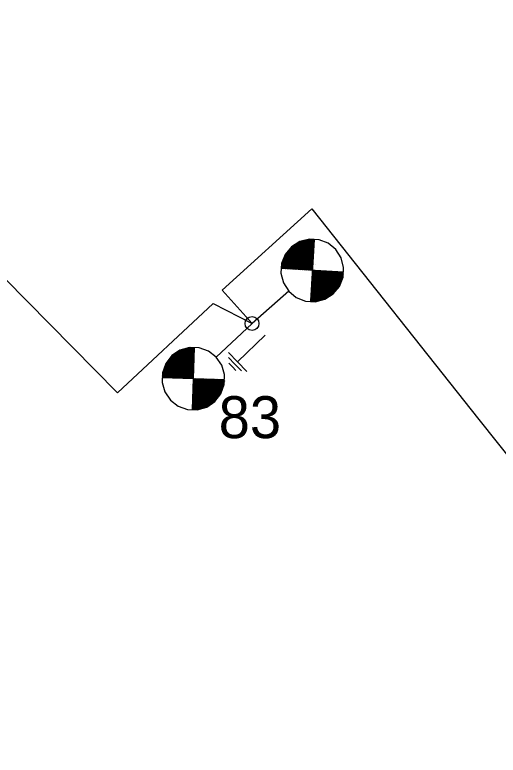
# Model space of a CAD drawing. Extents: x 25497851 to 25498523, y 6686544 to 6687372.
# Drawn here: x 25498375.6 to 25498410.2, y 6687202.5 to 6687255.4 of the extents above; entities that cross this region are included whole.
import ezdxf

# ---------------------------------------------------------------- set-up
doc = ezdxf.new("R2010")
doc.units = 0
for name, color, linetype in [('EL_CABLE_MAA', 7, 'Continuous'), ('KEYGWT_ANNOTATION', 7, 'Continuous'), ('Level 17', 7, 'Continuous'), ('Level 63', 7, 'Continuous'), ('Taso 1', 7, 'Continuous'), ('Taso 50', 7, 'Continuous')]:
    doc.layers.add(name, color=color, linetype=linetype)

msp = doc.modelspace()

# ---------------------------------------------------------------- linework, layer by layer
at = {"layer": 'EL_CABLE_MAA'}
for points in [[(25498357.846, 6687255.44), (25498370.073, 6687241.504), (25498382.973, 6687228.409), (25498389.816, 6687234.786), (25498392.6, 6687233.365)], [(25498392.6, 6687233.365), (25498390.456, 6687235.761), (25498396.873, 6687241.567), (25498408.81, 6687226.51), (25498414.146, 6687219.815), (25498426.734, 6687207.772), (25498433.268, 6687202.5), (25498436.712, 6687203.691)]]:
    msp.add_lwpolyline(points, dxfattribs=at)
at = {"layer": 'Level 17'}
for points in [[(25498393.533, 6687232.534), (25498391.572, 6687230.634)], [(25498391.572, 6687230.626), (25498390.914, 6687231.305)], [(25498391.383, 6687230.46), (25498390.917, 6687230.941)], [(25498392.23, 6687229.947), (25498391.572, 6687230.626)], [(25498390.936, 6687230.543), (25498391.194, 6687230.276)], [(25498391.194, 6687230.276), (25498391.452, 6687230.01)], [(25498391.849, 6687229.978), (25498391.383, 6687230.46)]]:
    msp.add_lwpolyline(points, dxfattribs=at)
at = {"layer": 'Taso 1'}
for p, q in [((25498397.052, 6687239.384), (25498396.773, 6687234.949)), ((25498399.13, 6687237.028), (25498394.695, 6687237.307)), ((25498395.225, 6687235.68), (25498392.6, 6687233.365)), ((25498390.048, 6687230.969), (25498392.6, 6687233.365)), ((25498388.338, 6687227.209), (25498388.478, 6687231.65)), ((25498386.188, 6687229.499), (25498390.63, 6687229.359))]:
    msp.add_line(p, q, dxfattribs=at)
for points in [[(25498398.599, 6687238.654), (25498398.057, 6687239.103), (25498397.403, 6687239.362), (25498396.7, 6687239.407), (25498396.019, 6687239.232), (25498395.424, 6687238.855), (25498394.976, 6687238.312), (25498394.717, 6687237.658), (25498394.673, 6687236.956), (25498394.848, 6687236.274), (25498395.225, 6687235.68), (25498395.768, 6687235.231), (25498396.422, 6687234.972), (25498397.124, 6687234.927), (25498397.806, 6687235.102), (25498398.4, 6687235.479), (25498398.849, 6687236.021), (25498399.108, 6687236.676), (25498399.152, 6687237.378), (25498398.977, 6687238.06)], [(25498386.769, 6687227.89), (25498387.326, 6687227.458), (25498387.988, 6687227.22), (25498388.691, 6687227.198), (25498389.367, 6687227.394), (25498389.949, 6687227.789), (25498390.38, 6687228.345), (25498390.619, 6687229.007), (25498390.641, 6687229.711), (25498390.444, 6687230.387), (25498390.048, 6687230.969), (25498389.492, 6687231.401), (25498388.83, 6687231.639), (25498388.127, 6687231.661), (25498387.451, 6687231.465), (25498386.869, 6687231.07), (25498386.437, 6687230.514), (25498386.199, 6687229.851), (25498386.177, 6687229.148), (25498386.374, 6687228.472)]]:
    msp.add_lwpolyline(points, close=True, dxfattribs=at)
msp.add_circle((25498392.6, 6687233.365), 0.5, dxfattribs=at)
at = {"layer": 'Taso 50'}
for p, q in [((25498395.721, 6687239.043), (25498396.942, 6687237.659)), ((25498396.948, 6687237.732), (25498395.791, 6687239.045)), ((25498395.829, 6687239.078), (25498396.953, 6687237.803)), ((25498395.866, 6687239.111), (25498396.957, 6687237.873)), ((25498395.904, 6687239.144), (25498396.962, 6687237.944)), ((25498395.941, 6687239.177), (25498396.966, 6687238.014)), ((25498396.971, 6687238.085), (25498395.979, 6687239.21)), ((25498396.975, 6687238.156), (25498396.049, 6687239.206)), ((25498396.98, 6687238.226), (25498396.087, 6687239.239)), ((25498396.984, 6687238.297), (25498396.157, 6687239.234)), ((25498396.988, 6687238.367), (25498396.195, 6687239.267)), ((25498396.993, 6687238.438), (25498396.265, 6687239.263)), ((25498396.997, 6687238.508), (25498396.303, 6687239.296)), ((25498397.002, 6687238.579), (25498396.374, 6687239.292)), ((25498397.006, 6687238.65), (25498396.411, 6687239.325)), ((25498397.011, 6687238.72), (25498396.482, 6687239.32)), ((25498397.015, 6687238.791), (25498396.519, 6687239.353)), ((25498397.02, 6687238.861), (25498396.59, 6687239.349)), ((25498397.024, 6687238.932), (25498396.627, 6687239.382)), ((25498397.028, 6687239.002), (25498396.698, 6687239.377)), ((25498397.033, 6687239.073), (25498396.768, 6687239.373)), ((25498397.037, 6687239.144), (25498396.806, 6687239.406)), ((25498397.042, 6687239.214), (25498396.876, 6687239.402)), ((25498397.046, 6687239.285), (25498396.98, 6687239.36)), ((25498396.348, 6687237.203), (25498395.191, 6687238.516)), ((25498396.419, 6687237.199), (25498395.2, 6687238.584)), ((25498396.49, 6687237.194), (25498395.233, 6687238.619)), ((25498396.56, 6687237.19), (25498395.271, 6687238.652)), ((25498396.631, 6687237.185), (25498395.308, 6687238.686)), ((25498396.701, 6687237.181), (25498395.346, 6687238.719)), ((25498396.772, 6687237.176), (25498395.383, 6687238.752)), ((25498395.388, 6687238.822), (25498396.842, 6687237.172)), ((25498395.424, 6687238.855), (25498396.913, 6687237.167)), ((25498395.463, 6687238.888), (25498396.917, 6687237.238)), ((25498395.533, 6687238.884), (25498396.922, 6687237.309)), ((25498395.571, 6687238.917), (25498396.926, 6687237.379)), ((25498395.608, 6687238.95), (25498396.931, 6687237.45)), ((25498395.646, 6687238.983), (25498396.902, 6687237.558)), ((25498396.94, 6687237.591), (25498395.683, 6687239.016)), ((25498395.572, 6687237.252), (25498394.878, 6687238.04)), ((25498395.643, 6687237.247), (25498394.915, 6687238.073)), ((25498395.713, 6687237.243), (25498394.92, 6687238.143)), ((25498395.784, 6687237.239), (25498394.957, 6687238.176)), ((25498395.854, 6687237.234), (25498394.962, 6687238.247)), ((25498395.925, 6687237.23), (25498394.999, 6687238.28)), ((25498395.996, 6687237.225), (25498395.037, 6687238.313)), ((25498396.066, 6687237.221), (25498395.074, 6687238.346)), ((25498396.137, 6687237.216), (25498395.079, 6687238.417)), ((25498396.207, 6687237.212), (25498395.116, 6687238.45)), ((25498396.278, 6687237.208), (25498395.154, 6687238.483)), ((25498394.866, 6687237.296), (25498394.701, 6687237.484)), ((25498394.937, 6687237.292), (25498394.706, 6687237.554)), ((25498395.008, 6687237.287), (25498394.743, 6687237.587)), ((25498395.078, 6687237.283), (25498394.747, 6687237.658)), ((25498395.149, 6687237.279), (25498394.752, 6687237.729)), ((25498395.219, 6687237.274), (25498394.789, 6687237.762)), ((25498395.29, 6687237.27), (25498394.794, 6687237.832)), ((25498395.36, 6687237.265), (25498394.831, 6687237.865)), ((25498395.431, 6687237.261), (25498394.836, 6687237.936)), ((25498395.502, 6687237.256), (25498394.873, 6687237.969)), ((25498397.118, 6687237.615), (25498397.118, 6687237.615)), ((25498394.796, 6687237.301), (25498394.697, 6687237.413)), ((25498396.9, 6687236.956), (25498398.255, 6687235.418)), ((25498396.904, 6687237.026), (25498398.293, 6687235.451)), ((25498396.909, 6687237.097), (25498398.363, 6687235.447)), ((25498396.912, 6687237.168), (25498398.4, 6687235.479)), ((25498396.984, 6687237.163), (25498398.438, 6687235.513)), ((25498397.054, 6687237.159), (25498398.443, 6687235.583)), ((25498397.125, 6687237.154), (25498398.48, 6687235.616)), ((25498397.195, 6687237.15), (25498398.518, 6687235.65)), ((25498397.266, 6687237.145), (25498398.555, 6687235.683)), ((25498397.336, 6687237.141), (25498398.593, 6687235.716)), ((25498397.407, 6687237.136), (25498398.625, 6687235.75)), ((25498397.478, 6687237.132), (25498398.635, 6687235.819)), ((25498397.548, 6687237.128), (25498398.672, 6687235.852)), ((25498397.619, 6687237.123), (25498398.71, 6687235.885)), ((25498397.689, 6687237.119), (25498398.747, 6687235.919)), ((25498397.76, 6687237.114), (25498398.785, 6687235.952)), ((25498397.83, 6687237.11), (25498398.822, 6687235.985)), ((25498397.901, 6687237.105), (25498398.849, 6687236.021)), ((25498397.972, 6687237.101), (25498398.864, 6687236.088)), ((25498398.042, 6687237.097), (25498398.869, 6687236.159)), ((25498398.113, 6687237.092), (25498398.906, 6687236.192)), ((25498398.183, 6687237.088), (25498398.911, 6687236.263)), ((25498398.254, 6687237.083), (25498398.948, 6687236.296)), ((25498398.324, 6687237.079), (25498398.953, 6687236.366)), ((25498398.395, 6687237.074), (25498398.99, 6687236.399)), ((25498398.466, 6687237.07), (25498398.995, 6687236.47)), ((25498398.536, 6687237.065), (25498399.032, 6687236.503)), ((25498398.607, 6687237.061), (25498399.037, 6687236.573)), ((25498398.677, 6687237.057), (25498399.074, 6687236.606)), ((25498398.748, 6687237.052), (25498399.113, 6687236.638)), ((25498398.818, 6687237.048), (25498399.083, 6687236.748)), ((25498398.889, 6687237.043), (25498399.087, 6687236.818)), ((25498398.96, 6687237.039), (25498399.125, 6687236.851)), ((25498399.03, 6687237.034), (25498399.129, 6687236.922)), ((25498396.864, 6687236.391), (25498397.922, 6687235.191)), ((25498396.869, 6687236.462), (25498397.96, 6687235.224)), ((25498396.873, 6687236.532), (25498397.997, 6687235.257)), ((25498396.877, 6687236.603), (25498398.035, 6687235.29)), ((25498396.882, 6687236.674), (25498398.103, 6687235.291)), ((25498396.886, 6687236.744), (25498398.143, 6687235.319)), ((25498396.891, 6687236.815), (25498398.18, 6687235.352)), ((25498396.895, 6687236.885), (25498398.218, 6687235.385)), ((25498396.833, 6687235.897), (25498397.56, 6687235.072)), ((25498396.837, 6687235.968), (25498397.631, 6687235.068)), ((25498396.842, 6687236.038), (25498397.669, 6687235.101)), ((25498396.846, 6687236.109), (25498397.739, 6687235.096)), ((25498396.851, 6687236.18), (25498397.806, 6687235.102)), ((25498396.855, 6687236.25), (25498397.847, 6687235.125)), ((25498396.86, 6687236.321), (25498397.885, 6687235.158)), ((25498396.798, 6687235.333), (25498397.128, 6687234.958)), ((25498396.802, 6687235.403), (25498397.199, 6687234.953)), ((25498396.806, 6687235.474), (25498397.236, 6687234.986)), ((25498396.811, 6687235.544), (25498397.307, 6687234.982)), ((25498396.815, 6687235.615), (25498397.344, 6687235.015)), ((25498396.82, 6687235.686), (25498397.415, 6687235.01)), ((25498396.824, 6687235.756), (25498397.472, 6687235.021)), ((25498396.829, 6687235.827), (25498397.523, 6687235.039)), ((25498396.78, 6687235.05), (25498396.879, 6687234.938)), ((25498396.784, 6687235.121), (25498396.95, 6687234.933)), ((25498396.789, 6687235.192), (25498397.02, 6687234.929)), ((25498396.793, 6687235.262), (25498397.091, 6687234.925)), ((25498388.464, 6687231.196), (25498388.053, 6687231.633)), ((25498388.466, 6687231.266), (25498388.124, 6687231.631)), ((25498388.468, 6687231.337), (25498388.16, 6687231.665)), ((25498388.47, 6687231.408), (25498388.231, 6687231.663)), ((25498388.473, 6687231.478), (25498388.302, 6687231.661)), ((25498388.475, 6687231.549), (25498388.372, 6687231.658)), ((25498388.41, 6687229.5), (25498386.904, 6687231.103)), ((25498388.413, 6687229.57), (25498386.975, 6687231.101)), ((25498388.415, 6687229.641), (25498387.012, 6687231.135)), ((25498388.417, 6687229.712), (25498387.048, 6687231.169)), ((25498388.419, 6687229.782), (25498387.084, 6687231.204)), ((25498388.422, 6687229.853), (25498387.121, 6687231.238)), ((25498388.424, 6687229.924), (25498387.16, 6687231.267)), ((25498388.426, 6687229.994), (25498387.228, 6687231.27)), ((25498388.428, 6687230.065), (25498387.265, 6687231.304)), ((25498388.43, 6687230.136), (25498387.301, 6687231.338)), ((25498388.433, 6687230.206), (25498387.337, 6687231.373)), ((25498388.435, 6687230.277), (25498387.374, 6687231.407)), ((25498388.437, 6687230.348), (25498387.41, 6687231.441)), ((25498388.439, 6687230.418), (25498387.451, 6687231.465)), ((25498388.442, 6687230.489), (25498387.517, 6687231.473)), ((25498388.444, 6687230.56), (25498387.588, 6687231.471)), ((25498388.446, 6687230.63), (25498387.625, 6687231.505)), ((25498388.448, 6687230.701), (25498387.695, 6687231.503)), ((25498388.45, 6687230.772), (25498387.732, 6687231.537)), ((25498388.453, 6687230.842), (25498387.782, 6687231.557)), ((25498388.455, 6687230.913), (25498387.839, 6687231.569)), ((25498388.457, 6687230.984), (25498387.909, 6687231.567)), ((25498388.459, 6687231.054), (25498387.946, 6687231.601)), ((25498388.462, 6687231.125), (25498388.017, 6687231.599)), ((25498387.56, 6687229.456), (25498386.499, 6687230.585)), ((25498387.631, 6687229.453), (25498386.536, 6687230.62)), ((25498387.702, 6687229.451), (25498386.572, 6687230.654)), ((25498387.772, 6687229.449), (25498386.608, 6687230.688)), ((25498387.843, 6687229.447), (25498386.645, 6687230.722)), ((25498387.914, 6687229.444), (25498386.653, 6687230.792)), ((25498387.984, 6687229.442), (25498386.684, 6687230.827)), ((25498388.055, 6687229.44), (25498386.72, 6687230.861)), ((25498388.126, 6687229.438), (25498386.756, 6687230.896)), ((25498388.196, 6687229.436), (25498386.793, 6687230.93)), ((25498388.267, 6687229.433), (25498386.829, 6687230.964)), ((25498388.338, 6687229.431), (25498386.832, 6687231.035)), ((25498388.409, 6687229.429), (25498386.869, 6687231.07)), ((25498386.853, 6687229.478), (25498386.306, 6687230.061)), ((25498386.924, 6687229.475), (25498386.308, 6687230.132)), ((25498386.995, 6687229.473), (25498386.344, 6687230.166)), ((25498387.065, 6687229.471), (25498386.347, 6687230.236)), ((25498387.136, 6687229.469), (25498386.383, 6687230.271)), ((25498387.207, 6687229.467), (25498386.385, 6687230.341)), ((25498387.277, 6687229.464), (25498386.422, 6687230.376)), ((25498387.348, 6687229.462), (25498386.424, 6687230.446)), ((25498387.419, 6687229.46), (25498386.437, 6687230.514)), ((25498387.489, 6687229.458), (25498386.463, 6687230.551)), ((25498386.288, 6687229.495), (25498386.185, 6687229.605)), ((25498386.359, 6687229.493), (25498386.188, 6687229.676)), ((25498386.571, 6687229.487), (25498386.193, 6687229.889)), ((25498386.429, 6687229.491), (25498386.224, 6687229.71)), ((25498386.5, 6687229.489), (25498386.226, 6687229.78)), ((25498386.641, 6687229.484), (25498386.231, 6687229.922)), ((25498386.712, 6687229.482), (25498386.267, 6687229.956)), ((25498386.783, 6687229.48), (25498386.269, 6687230.027)), ((25498388.395, 6687229.005), (25498389.696, 6687227.62)), ((25498389.768, 6687227.688), (25498388.399, 6687229.146)), ((25498389.805, 6687227.722), (25498388.402, 6687229.217)), ((25498389.841, 6687227.757), (25498388.404, 6687229.288)), ((25498389.912, 6687227.754), (25498388.406, 6687229.358)), ((25498389.949, 6687227.789), (25498388.408, 6687229.429)), ((25498389.732, 6687227.654), (25498388.431, 6687229.039)), ((25498389.985, 6687227.823), (25498388.479, 6687229.427)), ((25498388.55, 6687229.424), (25498389.987, 6687227.894)), ((25498388.62, 6687229.422), (25498390.024, 6687227.928)), ((25498388.691, 6687229.42), (25498390.06, 6687227.962)), ((25498388.762, 6687229.418), (25498390.097, 6687227.996)), ((25498388.832, 6687229.416), (25498390.133, 6687228.03)), ((25498388.903, 6687229.413), (25498390.165, 6687228.067)), ((25498388.974, 6687229.411), (25498390.172, 6687228.135)), ((25498389.044, 6687229.409), (25498390.208, 6687228.17)), ((25498389.115, 6687229.407), (25498390.245, 6687228.204)), ((25498389.186, 6687229.404), (25498390.281, 6687228.238)), ((25498389.256, 6687229.402), (25498390.283, 6687228.309)), ((25498389.327, 6687229.4), (25498390.32, 6687228.343)), ((25498389.398, 6687229.398), (25498390.356, 6687228.377)), ((25498389.468, 6687229.396), (25498390.393, 6687228.411)), ((25498389.539, 6687229.393), (25498390.395, 6687228.482)), ((25498389.61, 6687229.391), (25498390.431, 6687228.516)), ((25498389.68, 6687229.389), (25498390.433, 6687228.587)), ((25498389.751, 6687229.387), (25498390.47, 6687228.621)), ((25498389.822, 6687229.384), (25498390.472, 6687228.692)), ((25498389.892, 6687229.382), (25498390.509, 6687228.726)), ((25498389.963, 6687229.38), (25498390.511, 6687228.797)), ((25498390.034, 6687229.378), (25498390.547, 6687228.831)), ((25498390.104, 6687229.376), (25498390.549, 6687228.902)), ((25498390.175, 6687229.373), (25498390.586, 6687228.936)), ((25498390.246, 6687229.371), (25498390.588, 6687229.007)), ((25498390.317, 6687229.369), (25498390.59, 6687229.077)), ((25498390.387, 6687229.367), (25498390.627, 6687229.112)), ((25498390.458, 6687229.364), (25498390.629, 6687229.182)), ((25498390.529, 6687229.362), (25498390.631, 6687229.253)), ((25498388.217, 6687228.975), (25498388.217, 6687228.975)), ((25498388.379, 6687228.51), (25498389.406, 6687227.417)), ((25498389.443, 6687227.451), (25498388.382, 6687228.581)), ((25498389.479, 6687227.485), (25498388.384, 6687228.651)), ((25498389.516, 6687227.519), (25498388.386, 6687228.722)), ((25498389.552, 6687227.554), (25498388.388, 6687228.793)), ((25498388.39, 6687228.863), (25498389.588, 6687227.588)), ((25498389.658, 6687227.592), (25498388.395, 6687228.936)), ((25498388.362, 6687227.945), (25498388.978, 6687227.289)), ((25498388.364, 6687228.015), (25498389.014, 6687227.323)), ((25498388.366, 6687228.086), (25498389.085, 6687227.321)), ((25498388.368, 6687228.157), (25498389.121, 6687227.355)), ((25498388.371, 6687228.227), (25498389.192, 6687227.353)), ((25498388.373, 6687228.298), (25498389.228, 6687227.387)), ((25498388.375, 6687228.369), (25498389.299, 6687227.385)), ((25498388.377, 6687228.439), (25498389.336, 6687227.419)), ((25498388.346, 6687227.45), (25498388.586, 6687227.195)), ((25498388.348, 6687227.521), (25498388.622, 6687227.229)), ((25498388.351, 6687227.591), (25498388.693, 6687227.227)), ((25498388.353, 6687227.662), (25498388.763, 6687227.225)), ((25498388.355, 6687227.733), (25498388.8, 6687227.259)), ((25498388.357, 6687227.803), (25498388.871, 6687227.257)), ((25498388.359, 6687227.874), (25498388.907, 6687227.291)), ((25498388.342, 6687227.309), (25498388.41, 6687227.236)), ((25498388.344, 6687227.379), (25498388.515, 6687227.197))]:
    msp.add_line(p, q, dxfattribs=at)

# ---------------------------------------------------------------- texts
at = {"layer": 'KEYGWT_ANNOTATION'}
msp.add_text('83', height=3, dxfattribs=at).set_placement((25498390.217, 6687225.171))
at = {"layer": 'Level 63'}
msp.add_text('(C) KEYPRO 2000', height=0.0001, rotation=314.1, dxfattribs=at).set_placement((25498390.936, 6687230.542))

doc.saveas('drawing.dxf')
